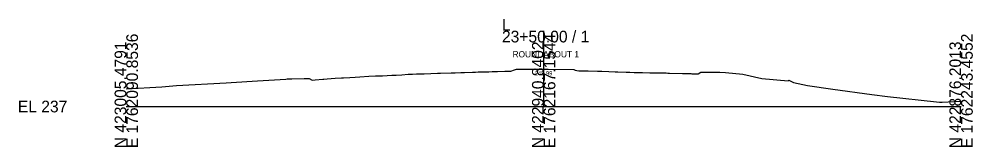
# Model space of a CAD drawing. Extents: x -26 to 3203, y -11010 to 4024.
# Drawn here: x -25.7 to 202.8, y -2509.7 to -2479 of the extents above; entities that cross this region are included whole.
import ezdxf

# ---------------------------------------------------------------- set-up
doc = ezdxf.new("R2010")
doc.units = 0
for name, color, linetype in [('Default', 7, 'Continuous'), ('Exist Cross Section Cell', 7, 'Continuous'), ('Exist XS Center Line Elevation Label', 7, 'Continuous'), ('Exist XS Ground Line', 7, 'Continuous'), ('Prop XS SE Text', 7, 'Continuous')]:
    doc.layers.add(name, color=color, linetype=linetype)

msp = doc.modelspace()

# ---------------------------------------------------------------- linework, layer by layer
at = {"layer": 'Exist Cross Section Cell'}
for p, q in [((100, -2500), (100, -2481.82)), ((0, -2500), (100, -2500)), ((100, -2500), (200, -2500))]:
    msp.add_line(p, q, dxfattribs=at)
at = {"layer": 'Exist XS Ground Line'}
msp.add_lwpolyline([(0, -2495.79), (8.48, -2495.27), (11.99, -2494.96), (23.95, -2494.33), (25.09, -2494.25), (31.45, -2493.83), (38.2, -2493.4), (38.52, -2493.39), (38.68, -2493.39), (38.98, -2493.38), (39.68, -2493.36), (42.65, -2493.27), (43.71, -2493.24), (43.83, -2493.3), (44.55, -2493.65), (45.25, -2493.58), (47.08, -2493.42), (47.32, -2493.4), (48.09, -2493.36), (48.1, -2493.36), (50.03, -2493.22), (51.52, -2493.13), (52.02, -2493.1), (53.56, -2493), (54.85, -2492.92), (55.94, -2492.85), (58.08, -2492.74), (59.69, -2492.67), (60.59, -2492.63), (61.37, -2492.6), (63.64, -2492.48), (64.14, -2492.46), (64.62, -2492.44), (66.05, -2492.36), (67.5, -2492.27), (67.8, -2492.26), (68.03, -2492.25), (68.6, -2492.22), (69.55, -2492.17), (71.36, -2492.13), (71.36, -2492.13), (71.37, -2492.13), (74.59, -2492.01), (74.9, -2492), (75.28, -2491.99), (77.8, -2491.93), (78.79, -2491.9), (80.12, -2491.85), (80.14, -2491.85), (81.06, -2491.81), (82.95, -2491.75), (83.66, -2491.72), (84.33, -2491.71), (85.51, -2491.68), (86.83, -2491.65), (87.64, -2491.63), (88.97, -2491.59), (90.68, -2491.54), (90.92, -2491.54), (91.01, -2491.53), (91.87, -2491.51), (92.09, -2491.51), (92.98, -2491.22), (93.45, -2491.06), (100.76, -2491), (100.85, -2491), (101.05, -2491.01), (107.25, -2491.11), (107.58, -2491.24), (107.93, -2491.38), (108.43, -2491.4), (108.7, -2491.41), (110.1, -2491.45), (110.69, -2491.47), (112.89, -2491.51), (113.71, -2491.53), (113.95, -2491.53), (115.64, -2491.58), (117.16, -2491.65), (117.47, -2491.66), (117.8, -2491.67), (119.76, -2491.72), (120.07, -2491.73), (120.63, -2491.76), (121.65, -2491.8), (122.8, -2491.82), (123.7, -2491.85), (125.46, -2491.88), (126.24, -2491.89), (126.92, -2491.91), (129.35, -2491.95), (129.76, -2491.96), (130.14, -2491.97), (133.26, -2492.06), (133.36, -2492.06), (133.58, -2492.07), (135.12, -2492.11), (135.23, -2492.11), (135.51, -2492.12), (137.04, -2492.19), (137.64, -2491.73), (137.65, -2491.72), (137.68, -2491.72), (142.23, -2491.79), (143.58, -2491.8), (147.71, -2492.25), (152.28, -2493.25), (158.57, -2493.8), (158.72, -2493.69), (159.87, -2494.23), (163.18, -2494.98), (169.26, -2495.8), (178.65, -2497.12), (182.37, -2497.63), (194.12, -2498.87), (194.85, -2498.94), (195.45, -2498.92), (196.9, -2498.87), (200, -2498.72)], dxfattribs=at)
msp.add_lwpolyline([(0, -2495.79), (8.48, -2495.27), (11.99, -2494.96), (23.95, -2494.33), (25.09, -2494.25), (31.45, -2493.83), (38.2, -2493.4), (38.52, -2493.39), (38.68, -2493.39), (38.98, -2493.38), (39.68, -2493.36), (42.65, -2493.27), (43.71, -2493.24), (43.83, -2493.3), (44.55, -2493.65), (45.25, -2493.58), (47.08, -2493.42), (47.32, -2493.4), (48.09, -2493.36), (48.1, -2493.36), (50.03, -2493.22), (51.52, -2493.13), (52.02, -2493.1), (53.56, -2493), (54.85, -2492.92), (55.94, -2492.85), (58.08, -2492.74), (59.69, -2492.67), (60.59, -2492.63), (61.37, -2492.6), (63.64, -2492.48), (64.14, -2492.46), (64.62, -2492.44), (66.05, -2492.36), (67.5, -2492.27), (67.8, -2492.26), (68.03, -2492.25), (68.6, -2492.22), (69.55, -2492.17), (71.36, -2492.13), (71.36, -2492.13), (71.37, -2492.13), (74.59, -2492.01), (74.9, -2492), (75.28, -2491.99), (77.8, -2491.93), (78.79, -2491.9), (80.12, -2491.85), (80.14, -2491.85), (81.06, -2491.81), (82.95, -2491.75), (83.66, -2491.72), (84.33, -2491.71), (85.51, -2491.68), (86.83, -2491.65), (87.64, -2491.63), (88.97, -2491.59), (90.68, -2491.54), (90.92, -2491.54), (91.01, -2491.53), (91.87, -2491.51), (92.09, -2491.51), (92.98, -2491.22), (93.45, -2491.06), (100.76, -2491), (100.85, -2491), (101.05, -2491.01), (107.25, -2491.11), (107.58, -2491.24), (107.93, -2491.38), (108.43, -2491.4), (108.7, -2491.41), (110.1, -2491.45), (110.69, -2491.47), (112.89, -2491.51), (113.71, -2491.53), (113.95, -2491.53), (115.64, -2491.58), (117.16, -2491.65), (117.47, -2491.66), (117.8, -2491.67), (119.76, -2491.72), (120.07, -2491.73), (120.63, -2491.76), (121.65, -2491.8), (122.8, -2491.82), (123.7, -2491.85), (125.46, -2491.88), (126.24, -2491.89), (126.92, -2491.91), (129.35, -2491.95), (129.76, -2491.96), (130.14, -2491.97), (133.26, -2492.06), (133.36, -2492.06), (133.58, -2492.07), (135.12, -2492.11), (135.23, -2492.11), (135.51, -2492.12), (137.04, -2492.19), (137.64, -2491.73), (137.65, -2491.72), (137.68, -2491.72), (142.23, -2491.79), (143.58, -2491.8), (147.71, -2492.25), (152.28, -2493.25), (158.57, -2493.8), (158.72, -2493.69), (159.87, -2494.23), (163.18, -2494.98), (169.26, -2495.8), (178.65, -2497.12), (182.37, -2497.63), (194.12, -2498.87), (194.85, -2498.94), (195.45, -2498.92), (196.9, -2498.87), (200, -2498.72)], dxfattribs=at)
msp.add_lwpolyline([(0, -2495.79), (8.48, -2495.27), (11.99, -2494.96), (23.95, -2494.33), (25.09, -2494.25), (31.45, -2493.83), (38.2, -2493.4), (38.52, -2493.39), (38.68, -2493.39), (38.98, -2493.38), (39.68, -2493.36), (42.65, -2493.27), (43.71, -2493.24), (43.83, -2493.3), (44.55, -2493.65), (45.25, -2493.58), (47.08, -2493.42), (47.32, -2493.4), (48.09, -2493.36), (48.1, -2493.36), (50.03, -2493.22), (51.52, -2493.13), (52.02, -2493.1), (53.56, -2493), (54.85, -2492.92), (55.94, -2492.85), (58.08, -2492.74), (59.69, -2492.67), (60.59, -2492.63), (61.37, -2492.6), (63.64, -2492.48), (64.14, -2492.46), (64.62, -2492.44), (66.05, -2492.36), (67.5, -2492.27), (67.8, -2492.26), (68.03, -2492.25), (68.6, -2492.22), (69.55, -2492.17), (71.36, -2492.13), (71.36, -2492.13), (71.37, -2492.13), (74.59, -2492.01), (74.9, -2492), (75.28, -2491.99), (77.8, -2491.93), (78.79, -2491.9), (80.12, -2491.85), (80.14, -2491.85), (81.06, -2491.81), (82.95, -2491.75), (83.66, -2491.72), (84.33, -2491.71), (85.51, -2491.68), (86.83, -2491.65), (87.64, -2491.63), (88.97, -2491.59), (90.68, -2491.54), (90.92, -2491.54), (91.01, -2491.53), (91.87, -2491.51), (92.09, -2491.51), (92.98, -2491.22), (93.45, -2491.06), (100.76, -2491), (100.85, -2491), (101.05, -2491.01), (107.25, -2491.11), (107.58, -2491.24), (107.93, -2491.38), (108.43, -2491.4), (108.7, -2491.41), (110.1, -2491.45), (110.69, -2491.47), (112.89, -2491.51), (113.71, -2491.53), (113.95, -2491.53), (115.64, -2491.58), (117.16, -2491.65), (117.47, -2491.66), (117.8, -2491.67), (119.76, -2491.72), (120.07, -2491.73), (120.63, -2491.76), (121.65, -2491.8), (122.8, -2491.82), (123.7, -2491.85), (125.46, -2491.88), (126.24, -2491.89), (126.92, -2491.91), (129.35, -2491.95), (129.76, -2491.96), (130.14, -2491.97), (133.26, -2492.06), (133.36, -2492.06), (133.58, -2492.07), (135.12, -2492.11), (135.23, -2492.11), (135.51, -2492.12), (137.04, -2492.19), (137.64, -2491.73), (137.65, -2491.72), (137.68, -2491.72), (142.23, -2491.79), (143.58, -2491.8), (147.71, -2492.25), (152.28, -2493.25), (158.57, -2493.8), (158.72, -2493.69), (159.87, -2494.23), (163.18, -2494.98), (169.26, -2495.8), (178.65, -2497.12), (182.37, -2497.63), (194.12, -2498.87), (194.85, -2498.94), (195.45, -2498.92), (196.9, -2498.87), (200, -2498.72)], dxfattribs=at)
msp.add_lwpolyline([(0, -2495.79), (8.48, -2495.27), (11.99, -2494.96), (23.95, -2494.33), (25.09, -2494.25), (31.45, -2493.83), (38.2, -2493.4), (38.52, -2493.39), (38.68, -2493.39), (38.98, -2493.38), (39.68, -2493.36), (42.65, -2493.27), (43.71, -2493.24), (43.83, -2493.3), (44.55, -2493.65), (45.25, -2493.58), (47.08, -2493.42), (47.32, -2493.4), (48.09, -2493.36), (48.1, -2493.36), (50.03, -2493.22), (51.52, -2493.13), (52.02, -2493.1), (53.56, -2493), (54.85, -2492.92), (55.94, -2492.85), (58.08, -2492.74), (59.69, -2492.67), (60.59, -2492.63), (61.37, -2492.6), (63.64, -2492.48), (64.14, -2492.46), (64.62, -2492.44), (66.05, -2492.36), (67.5, -2492.27), (67.8, -2492.26), (68.03, -2492.25), (68.6, -2492.22), (69.55, -2492.17), (71.36, -2492.13), (71.36, -2492.13), (71.37, -2492.13), (74.59, -2492.01), (74.9, -2492), (75.28, -2491.99), (77.8, -2491.93), (78.79, -2491.9), (80.12, -2491.85), (80.14, -2491.85), (81.06, -2491.81), (82.95, -2491.75), (83.66, -2491.72), (84.33, -2491.71), (85.51, -2491.68), (86.83, -2491.65), (87.64, -2491.63), (88.97, -2491.59), (90.68, -2491.54), (90.92, -2491.54), (91.01, -2491.53), (91.87, -2491.51), (92.09, -2491.51), (92.98, -2491.22), (93.45, -2491.06), (100.76, -2491), (100.85, -2491), (101.05, -2491.01), (107.25, -2491.11), (107.58, -2491.24), (107.93, -2491.38), (108.43, -2491.4), (108.7, -2491.41), (110.1, -2491.45), (110.69, -2491.47), (112.89, -2491.51), (113.71, -2491.53), (113.95, -2491.53), (115.64, -2491.58), (117.16, -2491.65), (117.47, -2491.66), (117.8, -2491.67), (119.76, -2491.72), (120.07, -2491.73), (120.63, -2491.76), (121.65, -2491.8), (122.8, -2491.82), (123.7, -2491.85), (125.46, -2491.88), (126.24, -2491.89), (126.92, -2491.91), (129.35, -2491.95), (129.76, -2491.96), (130.14, -2491.97), (133.26, -2492.06), (133.36, -2492.06), (133.58, -2492.07), (135.12, -2492.11), (135.23, -2492.11), (135.51, -2492.12), (137.04, -2492.19), (137.64, -2491.73), (137.65, -2491.72), (137.68, -2491.72), (142.23, -2491.79), (143.58, -2491.8), (147.71, -2492.25), (152.28, -2493.25), (158.57, -2493.8), (158.72, -2493.69), (159.87, -2494.23), (163.18, -2494.98), (169.26, -2495.8), (178.65, -2497.12), (182.37, -2497.63), (194.12, -2498.87), (194.85, -2498.94), (195.45, -2498.92), (196.9, -2498.87), (200, -2498.72)], dxfattribs=at)
msp.add_lwpolyline([(0, -2495.79), (8.48, -2495.27), (11.99, -2494.96), (23.95, -2494.33), (25.09, -2494.25), (31.45, -2493.83), (38.2, -2493.4), (38.52, -2493.39), (38.68, -2493.39), (38.98, -2493.38), (39.68, -2493.36), (42.65, -2493.27), (43.71, -2493.24), (43.83, -2493.3), (44.55, -2493.65), (45.25, -2493.58), (47.08, -2493.42), (47.32, -2493.4), (48.09, -2493.36), (48.1, -2493.36), (50.03, -2493.22), (51.52, -2493.13), (52.02, -2493.1), (53.56, -2493), (54.85, -2492.92), (55.94, -2492.85), (58.08, -2492.74), (59.69, -2492.67), (60.59, -2492.63), (61.37, -2492.6), (63.64, -2492.48), (64.14, -2492.46), (64.62, -2492.44), (66.05, -2492.36), (67.5, -2492.27), (67.8, -2492.26), (68.03, -2492.25), (68.6, -2492.22), (69.55, -2492.17), (71.36, -2492.13), (71.36, -2492.13), (71.37, -2492.13), (74.59, -2492.01), (74.9, -2492), (75.28, -2491.99), (77.8, -2491.93), (78.79, -2491.9), (80.12, -2491.85), (80.14, -2491.85), (81.06, -2491.81), (82.95, -2491.75), (83.66, -2491.72), (84.33, -2491.71), (85.51, -2491.68), (86.83, -2491.65), (87.64, -2491.63), (88.97, -2491.59), (90.68, -2491.54), (90.92, -2491.54), (91.01, -2491.53), (91.87, -2491.51), (92.09, -2491.51), (92.98, -2491.22), (93.45, -2491.06), (100.76, -2491), (100.85, -2491), (101.05, -2491.01), (107.25, -2491.11), (107.58, -2491.24), (107.93, -2491.38), (108.43, -2491.4), (108.7, -2491.41), (110.1, -2491.45), (110.69, -2491.47), (112.89, -2491.51), (113.71, -2491.53), (113.95, -2491.53), (115.64, -2491.58), (117.16, -2491.65), (117.47, -2491.66), (117.8, -2491.67), (119.76, -2491.72), (120.07, -2491.73), (120.63, -2491.76), (121.65, -2491.8), (122.8, -2491.82), (123.7, -2491.85), (125.46, -2491.88), (126.24, -2491.89), (126.92, -2491.91), (129.35, -2491.95), (129.76, -2491.96), (130.14, -2491.97), (133.26, -2492.06), (133.36, -2492.06), (133.58, -2492.07), (135.12, -2492.11), (135.23, -2492.11), (135.51, -2492.12), (137.04, -2492.19), (137.64, -2491.73), (137.65, -2491.72), (137.68, -2491.72), (142.23, -2491.79), (143.58, -2491.8), (147.71, -2492.25), (152.28, -2493.25), (158.57, -2493.8), (158.72, -2493.69), (159.87, -2494.23), (163.18, -2494.98), (169.26, -2495.8), (178.65, -2497.12), (182.37, -2497.63), (194.12, -2498.87), (194.85, -2498.94), (195.45, -2498.92), (196.9, -2498.87), (200, -2498.72)], dxfattribs=at)

# ---------------------------------------------------------------- texts
at = {"layer": 'Default'}
msp.add_text('-', height=0.0001, dxfattribs=at).set_placement((0, -2500))
at = {"layer": 'Exist Cross Section Cell'}
for s, p in [('L', (90, -2481.82)), ('23+50.00 / 1', (90, -2484.62)), ('EL 237', (-26, -2501.4))]:
    msp.add_text(s, height=2.8, dxfattribs=at).set_placement(p)
for s, p in [('E 1762090.8536', (2.8, -2510)), ('E 1762167.1544', (102.8, -2510)), ('E 1762243.4552', (202.8, -2510)), ('N 423005.4791', (0, -2510)), ('N 422940.8402', (100, -2510)), ('N 422876.2013', (200, -2510))]:
    msp.add_text(s, height=2.8, rotation=90, dxfattribs=at).set_placement(p)
at = {"layer": 'Exist XS Center Line Elevation Label'}
msp.add_text('245.99', height=1, dxfattribs=at).set_placement((97.87, -2492.51))
at = {"layer": 'Prop XS SE Text'}
msp.add_text('ROUNDABOUT 1', height=1.5, rotation=360, dxfattribs=at).set_placement((92.53, -2488.21))

doc.saveas('drawing.dxf')
